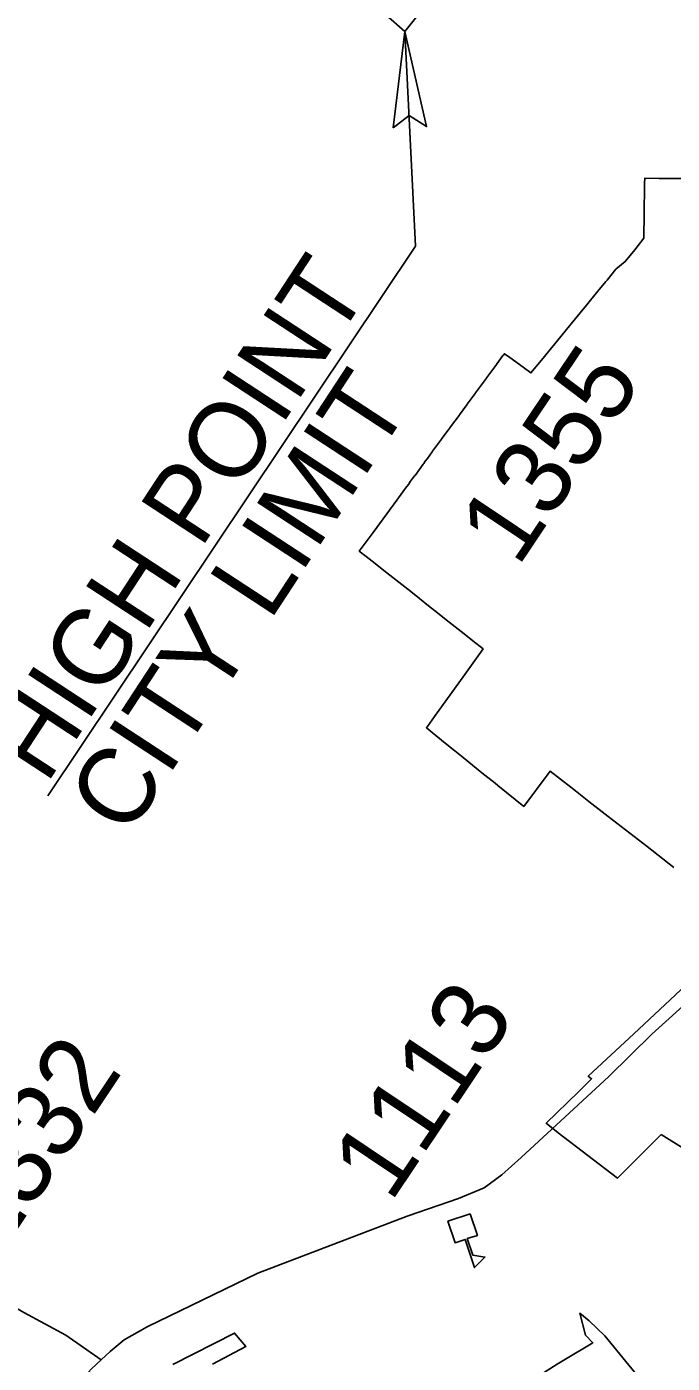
# Model space of a CAD drawing. Extents: x 1716282 to 1717158, y 799307 to 801078.
# Drawn here: x 1716496.5 to 1716557.2, y 800838.9 to 800964.6 of the extents above; entities that cross this region are included whole.
import ezdxf

# ---------------------------------------------------------------- set-up
doc = ezdxf.new("R2010")
doc.units = 0
for name, color, linetype in [('Exist Boundary Political City Limit New', 7, 'Continuous'), ('Exist Cultural Educational Facility High CELL', 7, 'Continuous'), ('Exist Road Secondary Type 51 Attributed', 7, 'Continuous'), ('Exist Road Secondary Type 51 Divided Attributed', 7, 'Continuous'), ('Map Preparation Boundary City Limit Buffer Line', 7, 'Continuous'), ('Old_Level_1', 7, 'Continuous'), ('Prop DSN Text', 7, 'Continuous'), ('Prop Terminator CELL', 7, 'Continuous')]:
    doc.layers.add(name, color=color, linetype=linetype)

msp = doc.modelspace()

# ---------------------------------------------------------------- linework, layer by layer
at = {"layer": 'Exist Boundary Political City Limit New'}
for points in [[(1716534.02, 800966.7), (1716532.02, 800964.18), (1716530.23, 800965.76)], [(1716557.33, 800885.53), (1716554.81, 800887.52), (1716551.15, 800890.35), (1716549.33, 800891.76), (1716548.07, 800892.74), (1716547.63, 800893.09), (1716545.69, 800894.59), (1716545.51, 800894.35), (1716543.21, 800891.28), (1716540.76, 800893.26), (1716540.52, 800893.46), (1716539.28, 800894.45), (1716537.51, 800895.88), (1716536.71, 800896.53), (1716535.83, 800897.24), (1716534.05, 800898.68), (1716534.15, 800898.82), (1716534.81, 800899.74), (1716537.5, 800903.48), (1716539.39, 800906.1), (1716538.43, 800906.87), (1716537.59, 800907.53), (1716536.76, 800908.18), (1716535.92, 800908.85), (1716535.08, 800909.51), (1716534.24, 800910.17), (1716533.41, 800910.83), (1716532.58, 800911.49), (1716531.73, 800912.16), (1716530.9, 800912.81), (1716530.06, 800913.47), (1716529.23, 800914.13), (1716528.38, 800914.8), (1716527.74, 800915.31), (1716528.39, 800916.18), (1716529.03, 800917.06), (1716530.92, 800919.63), (1716531.02, 800919.76), (1716532.09, 800921.22), (1716532.36, 800921.58), (1716532.57, 800921.87), (1716532.94, 800922.38), (1716532.98, 800922.43), (1716533.76, 800923.49), (1716533.8, 800923.55), (1716533.95, 800923.75), (1716534.14, 800924.01), (1716534.6, 800924.64), (1716534.64, 800924.69), (1716535.47, 800925.83), (1716535.51, 800925.88), (1716536.11, 800926.69), (1716536.29, 800926.93), (1716536.32, 800926.98), (1716537.12, 800928.06), (1716537.16, 800928.11), (1716537.86, 800929.07), (1716537.89, 800929.12), (1716538.64, 800930.13), (1716538.66, 800930.16), (1716538.67, 800930.18), (1716539.7, 800931.57), (1716539.73, 800931.62), (1716540.48, 800932.63), (1716541.25, 800933.69), (1716541.29, 800933.74), (1716541.39, 800933.87), (1716541.91, 800933.5), (1716543.14, 800932.6), (1716543.89, 800932.07), (1716545.03, 800933.46), (1716545.28, 800933.76), (1716546.41, 800935.14), (1716547.51, 800936.48), (1716547.67, 800936.69), (1716548.52, 800937.72), (1716549.27, 800938.63), (1716549.37, 800938.75), (1716550.19, 800939.76), (1716550.93, 800940.66), (1716551.04, 800940.79), (1716551.88, 800941.82), (1716552.76, 800942.53), (1716553.65, 800943.65), (1716554.51, 800944.74), (1716554.51, 800945), (1716554.54, 800946.84), (1716554.58, 800949.91), (1716554.59, 800950.37), (1716555.96, 800950.36), (1716558.26, 800950.34)]]:
    msp.add_lwpolyline(points, dxfattribs=at)
at = {"layer": 'Exist Cultural Educational Facility High CELL'}
msp.add_lwpolyline([(1716538.18, 800852.96), (1716538.85, 800850.94), (1716537.9, 800850.63), (1716538.41, 800849.08), (1716539.55, 800848.9), (1716538.58, 800847.91), (1716537.7, 800850.56), (1716536.75, 800850.25), (1716536.08, 800852.27)], close=True, dxfattribs=at)
at = {"layer": 'Exist Road Secondary Type 51 Attributed'}
for points in [[(1716503.46, 800839.23), (1716504.29, 800840), (1716505.63, 800841.12), (1716507.78, 800842.33), (1716518.18, 800847.39), (1716532.25, 800852.75), (1716537.08, 800854.4), (1716539.48, 800855.4), (1716541.16, 800856.63), (1716542.97, 800858.25), (1716551.2, 800865.89), (1716555.27, 800869.86), (1716562.39, 800876.32), (1716566.23, 800880.38)], [(1716460.9, 800863.59), (1716465.69, 800860.98), (1716469.05, 800859.24), (1716473.93, 800856.56), (1716479.27, 800853.53), (1716484.68, 800850.18), (1716489.95, 800847.3), (1716496.2, 800843.67), (1716500.12, 800841.54), (1716503.46, 800839.23)]]:
    msp.add_lwpolyline(points, dxfattribs=at)
at = {"layer": 'Exist Road Secondary Type 51 Divided Attributed'}
msp.add_lwpolyline([(1716418.82, 800745.94), (1716422.04, 800749.55), (1716427.19, 800754.32), (1716433.79, 800760.51), (1716436.9, 800763.35), (1716447.66, 800773.47), (1716450.59, 800776.43), (1716452.57, 800778.61), (1716465.81, 800796.02), (1716480.34, 800813), (1716493.75, 800828.38), (1716497.52, 800832.86), (1716498.85, 800834.32), (1716502.56, 800838.38), (1716503.46, 800839.23)], dxfattribs=at)
at = {"layer": 'Map Preparation Boundary City Limit Buffer Line'}
for points in [[(1716556.13, 800860.42), (1716558.29, 800859.09), (1716559.27, 800858.51), (1716559.47, 800858.57), (1716563.52, 800863.19), (1716559.81, 800866.14), (1716562.86, 800869.94), (1716559.7, 800873.27), (1716558.46, 800874.46), (1716553.57, 800869.91), (1716549.27, 800865.91), (1716549.59, 800865.67), (1716548.35, 800864.45), (1716545.33, 800861.49), (1716546.43, 800860.58), (1716552.03, 800856.33), (1716556.13, 800860.42)], [(1716549.35, 800842.9), (1716548.47, 800843.61), (1716549.02, 800841.55), (1716549.71, 800840.83), (1716546.98, 800839.21), (1716546.35, 800838.81), (1716538.76, 800834), (1716545.26, 800826.18), (1716545.31, 800826.11), (1716543.57, 800823.82), (1716544.54, 800822.97), (1716550.1, 800818), (1716551.47, 800820.13), (1716552.51, 800821.76), (1716547.25, 800826.48), (1716554.45, 800835.94), (1716555.38, 800835.27), (1716555.95, 800837.98), (1716554.21, 800837.35), (1716550.85, 800841.5), (1716549.35, 800842.9)], [(1716513.94, 800838.83), (1716517.06, 800840.48), (1716516.01, 800841.75), (1716510.19, 800838.79)]]:
    msp.add_lwpolyline(points, dxfattribs=at)
at = {"layer": 'Prop DSN Text'}
for p in [(1716532.02, 800964.18), (1716498.43, 800892.29)]:
    msp.add_line(p, (1716533.04, 800944), dxfattribs=at)
at = {"layer": 'Prop Terminator CELL'}
msp.add_lwpolyline([(1716530.92, 800955.12), (1716532.02, 800964.18), (1716534.07, 800955.23), (1716532.42, 800956.29)], close=True, dxfattribs=at)

# ---------------------------------------------------------------- texts
at = {"layer": 'Old_Level_1'}
for s, p in [('1355', (1716542.65, 800913.7)), ('1113', (1716530.69, 800853.92)), ('1332', (1716493.76, 800848.77))]:
    msp.add_text(s, height=7.128, rotation=56.2051, dxfattribs=at).set_placement(p)
at = {"layer": 'Prop DSN Text'}
for s, p in [('HIGH POINT', (1716498.31, 800893.27)), ('CITY LIMIT', (1716505.97, 800888.25))]:
    msp.add_text(s, height=7.128, rotation=56.7857, dxfattribs=at).set_placement(p)

doc.saveas('drawing.dxf')
